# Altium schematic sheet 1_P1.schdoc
size 307 x 218 mm; Symbol: Drawing-Symbol_A4; Device: Drawing-Symbol_A4; @Project Name: analog design projectt; @Page Count: 1; @Update Date: 2025-12-01; @Create Date: 2025-12-01; @Schematic Name: Schematic1; @Page No: 1; @Page Name: P1; Company: EasyEDA.com; Version: V1.0; Page Size: A4; @Create Time: 09:09:25; @Update Time: 10:07:45; Width: 1170; Height: 825; Region Start: 1; X Region Count: 6; Y Region Count: 4; Blade Width: 10; Title Block Position: 3; @Board Name: Board1
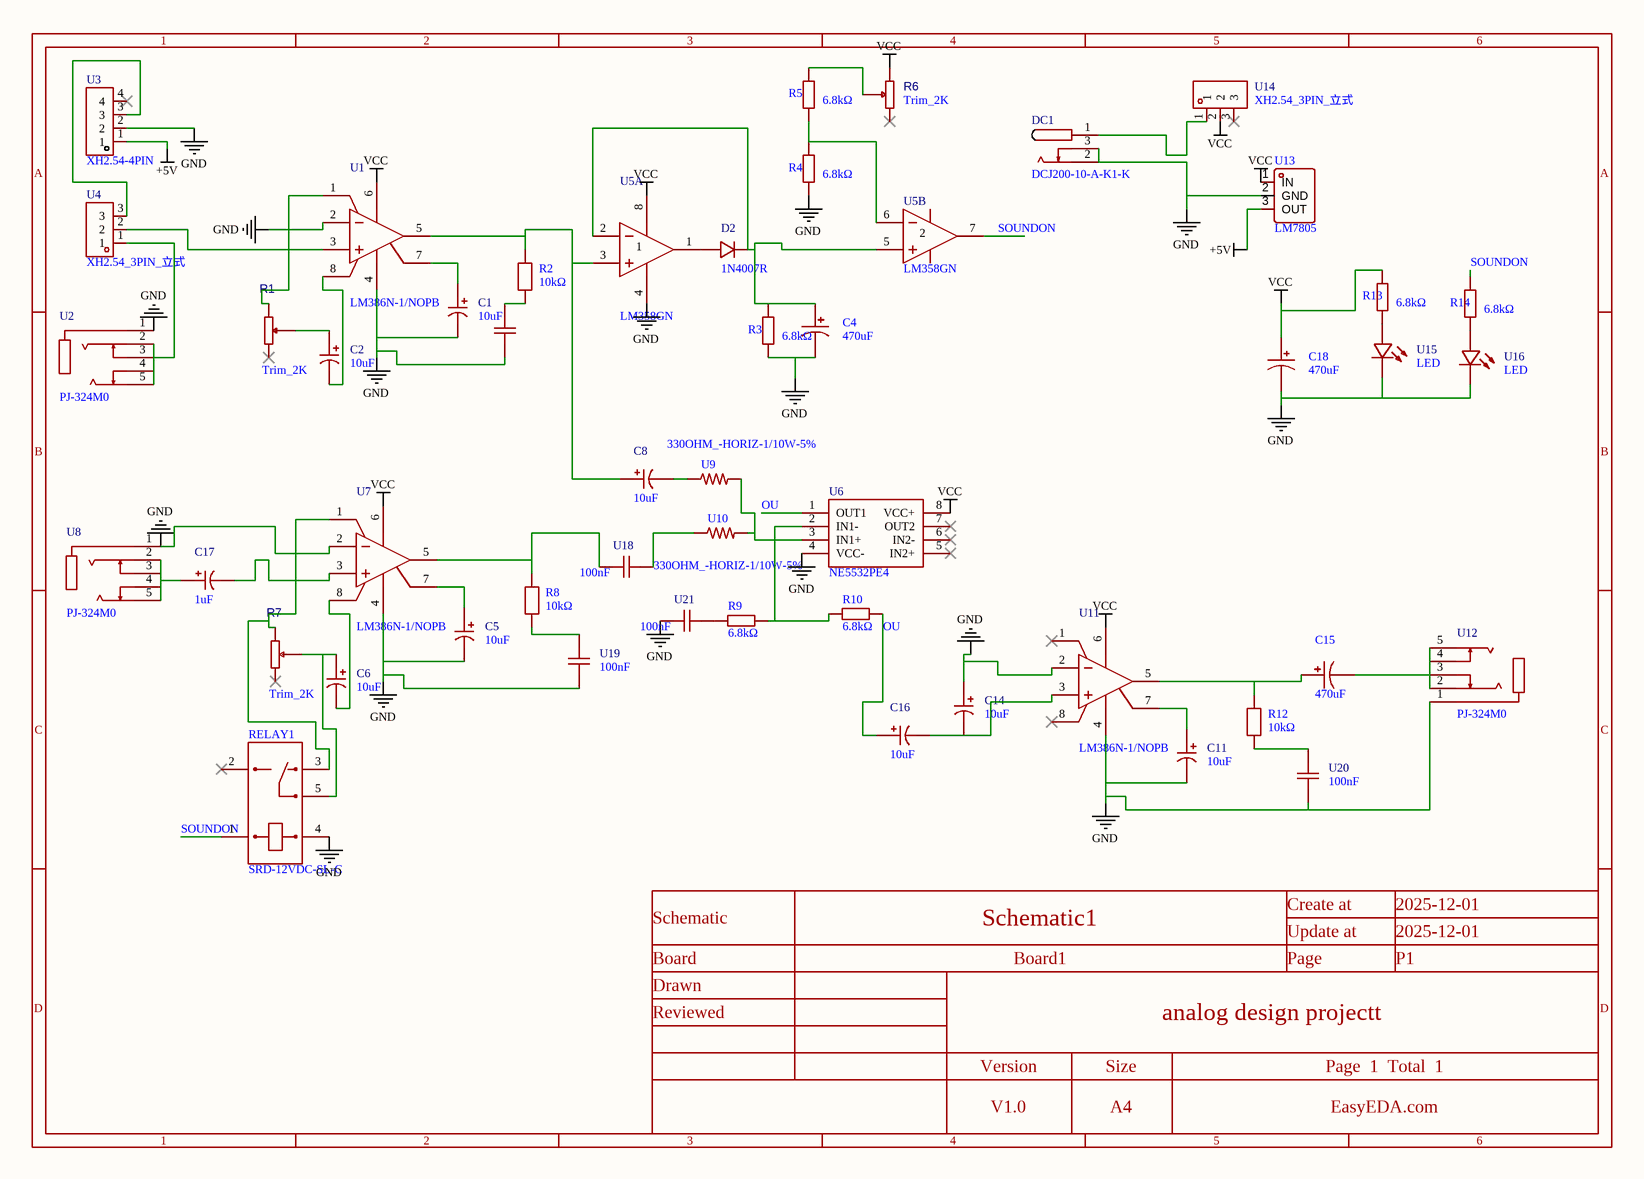
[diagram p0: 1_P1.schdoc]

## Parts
C1  10uF  [CAP-TH_BD5.0-P2.00-D0.5-FD]
C2  10uF  [CAP-TH_BD5.0-P2.00-D0.5-FD]
C4  470uF  [CAP-TH_BD8.0-P3.50-D0.6-FD]
C5  10uF  [CAP-TH_BD5.0-P2.00-D0.5-FD]
C6  10uF  [CAP-TH_BD5.0-P2.00-D0.5-FD]
C8  10uF  [CAP-TH_BD5.0-P2.00-D0.5-FD]
C11  10uF  [CAP-TH_BD5.0-P2.00-D0.5-FD]
C14  10uF  [CAP-TH_BD5.0-P2.00-D0.5-FD]
C15  470uF  [CAP-TH_BD8.0-P3.50-D0.6-FD]
C16  10uF  [CAP-TH_BD5.0-P2.00-D0.5-FD]
C17  1uF  [CAP-TH_BD5.0-P2.00-D0.5-FD]
C18  470uF  [CAP-TH_BD8.0-P3.50-D0.6-FD]
D2  1N4007R  [DO-41_BD2.4-L4.7-P8.70-D0.9-RD]
DC1  DCJ200-10-A-K1-K  [DC-IN-TH_DCJ200-10-A-K1-K]
R1  Trim_2K  [68W TRIMMER POT]
R2  10kΩ  [10K]
R3  6.8kΩ  [RES-TH_BD2.4-L6.3-P10.30-D0.6]
R4  6.8kΩ  [RES-TH_BD2.4-L6.3-P10.30-D0.6]
R5  6.8kΩ  [RES-TH_BD2.4-L6.3-P10.30-D0.6]
R6  Trim_2K  [68W TRIMMER POT]
R7  Trim_2K  [68W TRIMMER POT]
R8  10kΩ  [10K]
R9  6.8kΩ  [RES-TH_BD2.4-L6.3-P10.30-D0.6]
R10  6.8kΩ  [RES-TH_BD2.4-L6.3-P10.30-D0.6]
R12  10kΩ  [10K]
R13  6.8kΩ  [RES-TH_BD2.4-L6.3-P10.30-D0.6]
R14  6.8kΩ  [RES-TH_BD2.4-L6.3-P10.30-D0.6]
RELAY1  SRD-12VDC-SL-C  [RELAY-TH_SRD-XXVDC-XL-C]
U1  LM386N-1/NOPB  [DIP-8_L10.0-W6.5-P2.54-LS7.6-BL]
U2  PJ-324M0  [AUDIO-TH_PJ-324-M]
U3  XH2.54-4PIN  [CONN-TH_XH2.54-4]
U4  XH2.54_3PIN_立式  [CONN-TH_XH2.54_3PIN]
U5  LM358GN  [DIP-8_L9.8-W6.6-P2.54-LS7.6-BL]  (parts A,B of 2)
U6  NE5532PE4  [PDIP-8_L9.6-W6.4-P2.54-LS7.6-BL-1]
U7  LM386N-1/NOPB  [DIP-8_L10.0-W6.5-P2.54-LS7.6-BL]
U8  PJ-324M0  [AUDIO-TH_PJ-324-M]
U9  330OHM_-HORIZ-1/10W-5%  [AXIAL-0.3]
U10  330OHM_-HORIZ-1/10W-5%  [AXIAL-0.3]
U11  LM386N-1/NOPB  [DIP-8_L10.0-W6.5-P2.54-LS7.6-BL]
U12  PJ-324M0  [AUDIO-TH_PJ-324-M]
U13  LM7805  [TO-220-3_L10.0-W4.5-P2.54-L]
U14  XH2.54_3PIN_立式  [CONN-TH_XH2.54_3PIN]
U15  LED  [LED-TH_BD4.0-P2.54-FD_RED]
U16  LED  [LED-TH_BD4.0-P2.54-FD_RED]
U17  100nF  [CAP-TH_L5.0-W2.5-P5.00-D1.0]  (value not drawn)
U18  100nF  [CAP-TH_L5.0-W2.5-P5.00-D1.0]
U19  100nF  [CAP-TH_L5.0-W2.5-P5.00-D1.0]
U20  100nF  [CAP-TH_L5.0-W2.5-P5.00-D1.0]
U21  100nF  [CAP-TH_L5.0-W2.5-P5.00-D1.0]

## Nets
+5V: U3.1 U13.3(OUT)
GND: C1.2 C4.2 C5.2 C11.2 C14.1 C18.2 DC1.2 DC1.3 R3.1 R4.1 RELAY1.4 U1.2(IN-) U1.4(GND) U2.1 U3.2 U5.4(GND) U6.4(VCC-) U7.2(IN-) U7.4(GND) U8.1 U11.2(IN-) U11.4(GND) U12.1 U13.2(GND) U15.2(-) U16.2(-) U17.2 U19.1 U20.1 U21.1
VCC: C18.1 R6.3 R13.2 U1.6(VS) U5.8(VCC) U6.8(VCC+) U7.6(VS) U11.6(VS) U13.1(IN) U14.2
OU: C16.1 R10.1 U6.1(OUT1)
SOUNDON: R14.2 RELAY1.1 U5.7(OUT2)
NetC1_1: C1.1 U1.7(BYPASS)
NetC2_1: C2.1 R1.2
NetC2_2: C2.2 U1.8(GAIN)
NetC4_1: C4.1 D2.1(C) R3.2 U5.2(-IN1) U5.5(+IN2)
NetC5_1: C5.1 U7.7(BYPASS)
NetC6_1: C6.1 R7.2 RELAY1.5
NetC6_2: C6.2 U7.8(GAIN)
NetC8_1: C8.1 R2.2 U1.5(VOUT) U5.3(+IN1)
NetC8_2: C8.2 U9.P$1
NetC11_1: C11.1 U11.7(BYPASS)
NetC14_2: C14.2 C16.2 U11.3(IN+)
NetC15_1: C15.1 R12.2 U11.5(VOUT)
NetC15_2: C15.2 U12.2 U12.3 U12.4 U12.5
NetC17_1: C17.1 U8.2 U8.3 U8.4 U8.5
NetC17_2: C17.2 U7.3(IN+)
NetD2_2: D2.2(A) U5.1(OUT1)
NetDC1_1: DC1.1 U14.1
NetR1_1: R1.1 U1.1(GAIN) U1.3(IN+) U4.2
NetR2_1: R2.1 U17.1
NetR4_2: R4.2 R5.1 U5.6(-IN1)
NetR5_2: R5.2 R6.2
NetR7_1: R7.1 RELAY1.3 U7.1(GAIN)
NetR8_1: R8.1 U19.2
NetR8_2: R8.2 U7.5(VOUT) U18.1
NetR9_1: R9.1 R10.2 U6.2(IN1-)
NetR9_2: R9.2 U21.2
NetR12_1: R12.1 U20.2
NetR13_1: R13.1 U15.1(+)
NetR14_1: R14.1 U16.1(+)
NetU2_2: U2.2 U2.3 U2.4 U2.5 U4.1
NetU3_3: U3.3 U4.3
NetU6_3: U6.3(IN1+) U9.P$2 U10.P$2
NetU10_P$1: U10.P$1 U18.2

Not connected (* = marked no-connect by the designer): R1 3*; R6 1*; R7 3*; RELAY1 2*; U3 4*; U6 5(IN2+)* 6(IN2-)* 7(OUT2)*; U11 1(GAIN)* 8(GAIN)*; U14 3*

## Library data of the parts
C1 C2 C5 C6 C8 C11 C14 C16 C17 = RYHT25V10UF5*8: Manufacturer: HONOR(荣誉); Add into BOM: yes; Voltage Rating: 25V; Type: Polymer; Lifetime: 2000hrs@125℃
C4 C15 C18 = 470uF: Manufacturer: AISHI(艾华集团); Manufacturer Part: ERS1CM471F12OT; Add into BOM: yes; Tolerance: ±20%; Lifetime @ Temp: 7000hrs@105℃
D2 = 1N4007R: Manufacturer: PINGWEI(平伟); Add into BOM: yes; Diode Configuration: Independent Type; Forward Voltage (Vf@If): 1.3V@3A; Reverse Leakage Current (Ir): 5uA@1kV
DC1 = DCJ200-10-A-K1-K: Manufacturer: GCT; Add into BOM: yes
R1 R6 R7 = Trim_2K: Manufacturer Part: 68W trimmer potentiometer; Add into BOM: yes
R2 R8 R12 = 10K: Manufacturer: YAGEO(国巨); Manufacturer Part: MFR-25FTF52-10K; Add into BOM: yes; Tolerance: ±1%; Power(Watts): 250mW; Temperature Coefficient: ±100ppm/℃
R3-R5 R9 R10 R13 R14 = MFR-25JT-52-6K8: Manufacturer: YAGEO(国巨); Add into BOM: yes; Tolerance: ±5%; Power(Watts): 250mW
RELAY1 = SRD-12VDC-SL-C: Manufacturer: 松乐; Add into BOM: yes; Coil Voltage: 12V; Contact Form: One Conversion: 1C (SPDT-Conversion); Pin Number: 5; Maximum Switching Voltage: 250V@AC; Coil Rated Power: 360mW; Maximum Switching Current: 15A; Coil Type: Non-polar - Single Coil; Coil Resistance: 400Ω; Contact Resistance: 100mΩ; Operate Time: 10ms
U1 U7 U11 = LM386N-1/NOPB: Manufacturer: TI(德州仪器); Add into BOM: yes; Class: AB Class Amplifier; Speaker Channels: Monaural; Output Power: 325mWx1@8Ω; Voltage - Supply: 4V~12V
U2 U8 U12 = PJ-324M0: Manufacturer: XKB Connection(中国星坤); Add into BOM: yes; Connector Type: 3.5mm Headphone Jack; Current Rating: 500mA; Voltage Rating (Max): 30V
U3 = XH2.54-4PIN: Add into BOM: yes
U4 U14 = XH2.54_3PIN_立式: Add into BOM: yes
U5 = LM358GN: Manufacturer: HTC; Add into BOM: yes; Number of Channels: 2; Maximum Power Supply Range (Vdd-Vss): 45V; Gain Bandwidth Product: 700kHz; Vos - Input Offset Voltage: 7mV; Input Offset Voltage Drift(Vos TC): 9uV/℃; Slew Rate: 700V/ms; Ib - Input Bias Current: 20nA; Input Offset Current(Ios): 2nA; Common Mode Rejection Ratio(CMRR): 15dB; Input offset current drift(Ios TC): 10pA/℃; Quiescent Current: 1mA; Output Current: 50mA; Single supply: 5V~40V; Dual Supply: -22.5V~22.5V; Relevance: []
U6 = NE5532: Manufacturer: TI(德州仪器); Add into BOM: yes
U9 U10 = 330OHM_-HORIZ-1/10W-5%: Add into BOM: yes
U13 = LM7805: Manufacturer: TF; Add into BOM: yes
U15 U16 = LED: Symbol: LED_C9900015665; Add into BOM: yes
U17-U21 = 100nF: Symbol: 100NF_C9900015256; Add into BOM: yes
